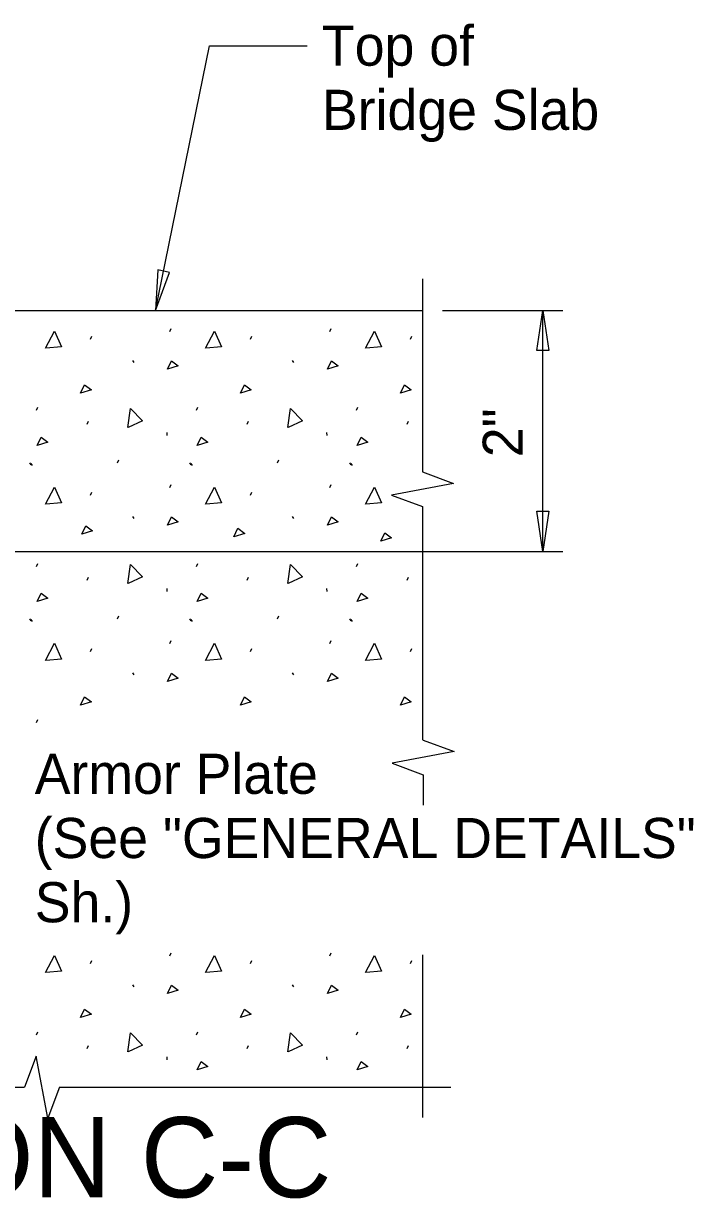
# Model space of a CAD drawing. Extents: x 2799.7 to 2896, y 515.2 to 573.9.
# Drawn here: x 2859.04 to 2864.61, y 557.93 to 567.69 of the extents above; entities that cross this region are included whole.
import ezdxf

# ---------------------------------------------------------------- set-up
doc = ezdxf.new("R2010")
doc.units = 0
for name, color, linetype in [('BR_AUTO DIMENSION', 7, 'Continuous'), ('BR_CONCRETE', 7, 'Continuous'), ('BR_DETAILS', 7, 'Continuous'), ('BR_TEXT', 7, 'Continuous')]:
    doc.layers.add(name, color=color, linetype=linetype)

msp = doc.modelspace()

# ---------------------------------------------------------------- linework, layer by layer
at = {"layer": 'BR_AUTO DIMENSION'}
for p, q in [((2860.1375, 565.3077), (2860.5841, 567.5063)), ((2860.5841, 567.5063), (2861.3973, 567.5063)), ((2862.5222, 565.3077), (2863.5226, 565.3077)), ((2863.3559, 563.3076), (2863.3559, 565.3077)), ((2857.6016, 563.3076), (2863.5226, 563.3076))]:
    msp.add_line(p, q, dxfattribs=at)
for points in [[(2860.1549, 565.6443), (2860.1375, 565.3077), (2860.2529, 565.6244)], [(2863.3059, 564.9743), (2863.3559, 565.3077), (2863.4059, 564.9743)], [(2863.4059, 563.6409), (2863.3559, 563.3076), (2863.3059, 563.6409)]]:
    msp.add_lwpolyline(points, close=True, dxfattribs=at)
at = {"layer": 'BR_CONCRETE'}
msp.add_line((2858.1016, 565.3077), (2862.3556, 565.3077), dxfattribs=at)
at = {"layer": 'BR_DETAILS'}
for p, q in [((2862.3556, 565.5706), (2862.3556, 563.9681)), ((2859.5973, 565.0699), (2859.6084, 565.0949)), ((2860.255, 565.1338), (2860.2661, 565.1587)), ((2860.9267, 565.0699), (2860.9378, 565.0949)), ((2861.5844, 565.1338), (2861.5955, 565.1587)), ((2862.256, 565.0699), (2862.2671, 565.0949)), ((2859.9442, 564.8923), (2859.9553, 564.8757)), ((2861.2736, 564.8923), (2861.2847, 564.8757)), ((2859.1477, 564.4788), (2859.1588, 564.5038)), ((2860.4771, 564.4788), (2860.4882, 564.5038)), ((2861.8064, 564.4788), (2861.8176, 564.5038)), ((2859.5695, 564.365), (2859.5807, 564.39)), ((2860.8989, 564.365), (2860.91, 564.39)), ((2862.2283, 564.365), (2862.2394, 564.39)), ((2860.2294, 564.2953), (2860.2321, 564.2704)), ((2861.5587, 564.2953), (2861.5615, 564.2704)), ((2859.0894, 564.0431), (2859.1005, 564.0265)), ((2859.1005, 564.0368), (2859.1116, 564.0201)), ((2859.8221, 564.0431), (2859.8332, 564.0681)), ((2860.4188, 564.0431), (2860.4299, 564.0265)), ((2860.4299, 564.0368), (2860.441, 564.0201)), ((2861.1515, 564.0431), (2861.1626, 564.0681)), ((2861.7481, 564.0431), (2861.7592, 564.0265)), ((2861.7592, 564.0368), (2861.7703, 564.0201)), ((2859.5973, 563.7736), (2859.6084, 563.7986)), ((2860.255, 563.8374), (2860.2661, 563.8624)), ((2860.9267, 563.7736), (2860.9378, 563.7986)), ((2861.5844, 563.8374), (2861.5955, 563.8624)), ((2862.3556, 563.6787), (2862.3556, 561.7408)), ((2859.9442, 563.596), (2859.9553, 563.5793)), ((2861.2736, 563.596), (2861.2847, 563.5793)), ((2859.1477, 563.1825), (2859.1588, 563.2074)), ((2860.4771, 563.1825), (2860.4882, 563.2074)), ((2861.8064, 563.1825), (2861.8176, 563.2074)), ((2859.5695, 563.0687), (2859.5807, 563.0937)), ((2860.8989, 563.0687), (2860.91, 563.0937)), ((2862.2283, 563.0687), (2862.2394, 563.0937)), ((2860.2294, 562.999), (2860.2321, 562.974)), ((2861.5587, 562.999), (2861.5615, 562.974)), ((2859.0894, 562.7468), (2859.1005, 562.7301)), ((2859.1005, 562.7404), (2859.1116, 562.7238)), ((2859.8221, 562.7468), (2859.8332, 562.7717)), ((2860.4188, 562.7468), (2860.4299, 562.7301)), ((2860.4299, 562.7404), (2860.441, 562.7238)), ((2861.1515, 562.7468), (2861.1626, 562.7717)), ((2861.7481, 562.7468), (2861.7592, 562.7301)), ((2861.7592, 562.7404), (2861.7703, 562.7238)), ((2860.255, 562.541), (2860.2661, 562.566)), ((2861.5844, 562.541), (2861.5955, 562.566)), ((2859.5973, 562.4772), (2859.6084, 562.5022)), ((2860.9267, 562.4772), (2860.9378, 562.5022)), ((2862.256, 562.4772), (2862.2671, 562.5022)), ((2859.9442, 562.2996), (2859.9553, 562.283)), ((2861.2736, 562.2996), (2861.2847, 562.283)), ((2859.1477, 561.8861), (2859.1588, 561.9111)), ((2862.3613, 561.4514), (2862.3613, 561.1995)), ((2859.5973, 559.8845), (2859.6084, 559.9095)), ((2860.255, 559.9483), (2860.2661, 559.9733)), ((2860.9267, 559.8845), (2860.9378, 559.9095)), ((2861.5844, 559.9483), (2861.5955, 559.9733)), ((2862.256, 559.8845), (2862.2671, 559.9095)), ((2862.3556, 559.9583), (2862.3556, 558.6061)), ((2859.9442, 559.7069), (2859.9553, 559.6902)), ((2861.2736, 559.7069), (2861.2847, 559.6902)), ((2859.1477, 559.2934), (2859.1588, 559.3184)), ((2860.4771, 559.2934), (2860.4882, 559.3184)), ((2861.8064, 559.2934), (2861.8176, 559.3184)), ((2859.5695, 559.1796), (2859.5807, 559.2046)), ((2860.8989, 559.1796), (2860.91, 559.2046)), ((2862.2283, 559.1796), (2862.2394, 559.2046)), ((2860.2294, 559.1099), (2860.2321, 559.0849)), ((2861.5587, 559.1099), (2861.5615, 559.0849)), ((2855.4311, 558.8577), (2859.049, 558.8577)), ((2859.3384, 558.8577), (2862.5903, 558.8577))]:
    msp.add_line(p, q, dxfattribs=at)
for points in [[(2859.2227, 564.995), (2859.2976, 565.1365), (2859.3559, 565.0061), (2859.2254, 564.995)], [(2860.552, 564.995), (2860.6269, 565.1365), (2860.6852, 565.0061), (2860.5548, 564.995)], [(2861.8814, 564.995), (2861.9563, 565.1365), (2862.0146, 565.0061), (2861.8842, 564.995)], [(2860.2356, 564.8202), (2860.2689, 564.8896), (2860.3244, 564.8479), (2860.2356, 564.8202)], [(2861.565, 564.8202), (2861.5983, 564.8896), (2861.6538, 564.8479), (2861.565, 564.8202)], [(2859.5146, 564.6218), (2859.5479, 564.6912), (2859.6034, 564.6495), (2859.5146, 564.6218)], [(2860.844, 564.6218), (2860.8773, 564.6912), (2860.9328, 564.6495), (2860.844, 564.6218)], [(2862.1733, 564.6218), (2862.2066, 564.6912), (2862.2621, 564.6495), (2862.1733, 564.6218)], [(2859.9072, 564.3363), (2859.9292, 564.4949), (2860.0286, 564.3923), (2859.9098, 564.3373)], [(2861.2365, 564.3363), (2861.2585, 564.4949), (2861.3579, 564.3923), (2861.2391, 564.3373)], [(2859.1533, 564.1874), (2859.1866, 564.2568), (2859.2421, 564.2152), (2859.1533, 564.1874)], [(2860.4826, 564.1874), (2860.5159, 564.2568), (2860.5714, 564.2152), (2860.4826, 564.1874)], [(2861.812, 564.1874), (2861.8453, 564.2568), (2861.9008, 564.2152), (2861.812, 564.1874)], [(2862.3556, 563.9681), (2862.6128, 563.8716), (2862.0983, 563.7751), (2862.3556, 563.6787)], [(2859.2227, 563.6987), (2859.2976, 563.8402), (2859.3559, 563.7098), (2859.2254, 563.6987)], [(2860.552, 563.6987), (2860.6269, 563.8402), (2860.6852, 563.7098), (2860.5548, 563.6987)], [(2861.8814, 563.6987), (2861.9563, 563.8402), (2862.0146, 563.7098), (2861.8842, 563.6987)], [(2859.5241, 563.4511), (2859.5574, 563.5205), (2859.6129, 563.4788), (2859.5241, 563.4511)], [(2860.2356, 563.5238), (2860.2689, 563.5932), (2860.3244, 563.5516), (2860.2356, 563.5238)], [(2861.565, 563.5238), (2861.5983, 563.5932), (2861.6538, 563.5516), (2861.565, 563.5238)], [(2860.7888, 563.4295), (2860.8221, 563.4988), (2860.8776, 563.4572), (2860.7888, 563.4295)], [(2862.0095, 563.3933), (2862.0428, 563.4627), (2862.0983, 563.421), (2862.0095, 563.3933)], [(2859.9072, 563.04), (2859.9292, 563.1986), (2860.0286, 563.096), (2859.9098, 563.0409)], [(2861.2365, 563.04), (2861.2585, 563.1986), (2861.3579, 563.096), (2861.2391, 563.0409)], [(2859.1533, 562.8911), (2859.1866, 562.9605), (2859.2421, 562.9188), (2859.1533, 562.8911)], [(2860.4826, 562.8911), (2860.5159, 562.9605), (2860.5714, 562.9188), (2860.4826, 562.8911)], [(2861.812, 562.8911), (2861.8453, 562.9605), (2861.9008, 562.9188), (2861.812, 562.8911)], [(2859.2227, 562.4023), (2859.2976, 562.5438), (2859.3559, 562.4134), (2859.2254, 562.4023)], [(2860.552, 562.4023), (2860.6269, 562.5438), (2860.6852, 562.4134), (2860.5548, 562.4023)], [(2861.8814, 562.4023), (2861.9563, 562.5438), (2862.0146, 562.4134), (2861.8842, 562.4023)], [(2860.2356, 562.2275), (2860.2689, 562.2968), (2860.3244, 562.2552), (2860.2356, 562.2275)], [(2861.565, 562.2275), (2861.5983, 562.2968), (2861.6538, 562.2552), (2861.565, 562.2275)], [(2859.5146, 562.0291), (2859.5479, 562.0985), (2859.6034, 562.0568), (2859.5146, 562.0291)], [(2860.844, 562.0291), (2860.8773, 562.0985), (2860.9328, 562.0568), (2860.844, 562.0291)], [(2862.1733, 562.0291), (2862.2066, 562.0985), (2862.2621, 562.0568), (2862.1733, 562.0291)], [(2862.3613, 561.7408), (2862.6186, 561.6443), (2862.1041, 561.5479), (2862.3613, 561.4514)], [(2859.2227, 559.8096), (2859.2976, 559.9511), (2859.3559, 559.8207), (2859.2254, 559.8096)], [(2860.552, 559.8096), (2860.6269, 559.9511), (2860.6852, 559.8207), (2860.5548, 559.8096)], [(2861.8814, 559.8096), (2861.9563, 559.9511), (2862.0146, 559.8207), (2861.8842, 559.8096)], [(2860.2356, 559.6347), (2860.2689, 559.7041), (2860.3244, 559.6625), (2860.2356, 559.6347)], [(2861.565, 559.6347), (2861.5983, 559.7041), (2861.6538, 559.6625), (2861.565, 559.6347)], [(2859.5146, 559.4364), (2859.5479, 559.5057), (2859.6034, 559.4641), (2859.5146, 559.4364)], [(2860.844, 559.4364), (2860.8773, 559.5057), (2860.9328, 559.4641), (2860.844, 559.4364)], [(2862.1733, 559.4364), (2862.2066, 559.5057), (2862.2621, 559.4641), (2862.1733, 559.4364)], [(2859.9072, 559.1509), (2859.9292, 559.3095), (2860.0286, 559.2069), (2859.9098, 559.1518)], [(2861.2365, 559.1509), (2861.2585, 559.3095), (2861.3579, 559.2069), (2861.2391, 559.1518)], [(2859.3384, 558.8577), (2859.242, 558.6004), (2859.1455, 559.1149), (2859.049, 558.8577)], [(2860.4826, 559.002), (2860.5159, 559.0714), (2860.5714, 559.0297), (2860.4826, 559.002)], [(2861.812, 559.002), (2861.8453, 559.0714), (2861.9008, 559.0297), (2861.812, 559.002)]]:
    msp.add_lwpolyline(points, dxfattribs=at)

# ---------------------------------------------------------------- texts
at = {"layer": 'BR_AUTO DIMENSION'}
msp.add_text('2"', height=0.33335, rotation=90, dxfattribs=at).set_placement((2863.1892, 564.0892))
at = {"layer": 'BR_TEXT'}
for s, height, p in [('Top of ', 0.33332, (2861.5197, 567.3405)), ('Bridge Slab', 0.333317, (2861.5197, 566.8072)), ('Armor Plate', 0.333317, (2859.133, 561.2938)), ('(See "GENERAL DETAILS"', 0.333317, (2859.133, 560.7605)), ('Sh.)', 0.33332, (2859.133, 560.2272)), ('SECTION C-C', 0.666733, (2855.8033, 557.9429))]:
    msp.add_text(s, height=height, dxfattribs=at).set_placement(p)

doc.saveas('drawing.dxf')
